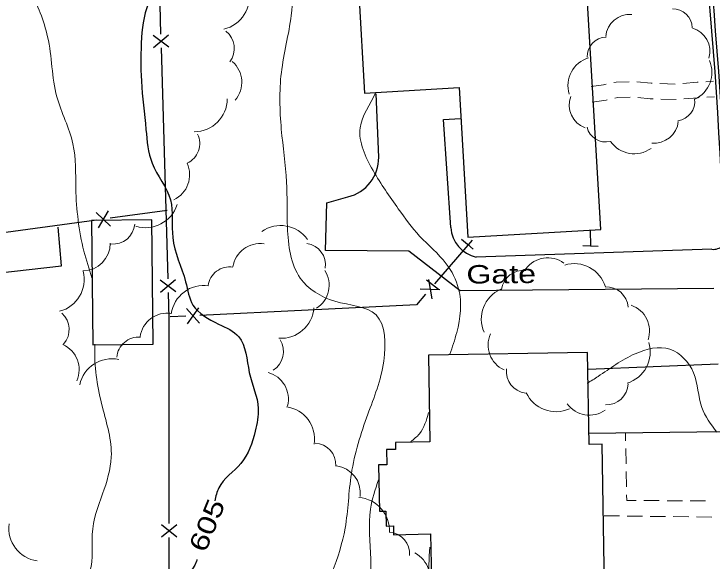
# Model space of a CAD drawing. Extents: x 2361708 to 2370558, y 6977955 to 6991887.
# Drawn here: x 2370196.5 to 2370378, y 6990815 to 6990957.1 of the extents above; entities that cross this region are included whole.
import ezdxf
from ezdxf.enums import TextEntityAlignment as Align

# ---------------------------------------------------------------- set-up
doc = ezdxf.new("R2010")
doc.units = 0
doc.header["$LTSCALE"] = 1.9
for name, color, linetype, lineweight in [('11', 7, 'Continuous', 25), ('13', 7, 'Continuous', 13), ('17', 7, 'Continuous', 25), ('18', 7, 'Continuous', 25), ('2', 7, 'Continuous', 25), ('29', 7, 'Continuous', 13), ('31', 7, 'Continuous', 13), ('35', 7, 'Continuous', 13)]:
    doc.layers.add(name, color=color, linetype=linetype, lineweight=lineweight)

msp = doc.modelspace()

# ---------------------------------------------------------------- linework, layer by layer
at = {"layer": '11'}
for points in [[(2370349.087, 6990901.122), (2370345.238, 6990966.068), (2370320.731, 6990964.615), (2370320.659, 6990965.934), (2370308.225, 6990965.206), (2370308.309, 6990963.716), (2370286.16, 6990962.425), (2370287.667, 6990936.559), (2370312.244, 6990937.983), (2370314.504, 6990899.112)], [(2370232.675, 6990871.312), (2370232.347, 6990903.64), (2370216.668, 6990903.481), (2370216.996, 6990871.153)], [(2370305.237, 6990802.129), (2370350.142, 6990802.887), (2370349.418, 6990845.332), (2370346.018, 6990845.27), (2370345.601, 6990869.157), (2370304.236, 6990868.433), (2370304.62, 6990845.956), (2370295.691, 6990845.8), (2370295.728, 6990843.991), (2370293.359, 6990843.948), (2370293.426, 6990839.979), (2370291.287, 6990839.938), (2370291.511, 6990827.91), (2370293.171, 6990827.946), (2370293.248, 6990824.036), (2370295.148, 6990824.074), (2370295.199, 6990821.785), (2370304.768, 6990822.006)]]:
    msp.add_lwpolyline(points, close=True, dxfattribs=at)
at = {"layer": '13'}
for p, q in [((2370368.429, 6990938.887), (2370364.427, 6990939.039)), ((2370378.402, 6990939.612), (2370376.403, 6990939.503)), ((2370378.63, 6990935.594), (2370376.631, 6990935.485)), ((2370368.657, 6990934.849), (2370364.655, 6990934.991)), ((2370355.511, 6990848.21), (2370355.54, 6990846.21)), ((2370355.579, 6990844.21), (2370355.647, 6990840.211)), ((2370355.676, 6990838.211), (2370355.744, 6990834.212)), ((2370360.288, 6990830.675), (2370364.289, 6990830.663)), ((2370366.288, 6990830.652), (2370370.289, 6990830.64)), ((2370372.289, 6990830.629), (2370376.289, 6990830.617)), ((2370353.926, 6990826.674), (2370349.925, 6990826.716)), ((2370359.927, 6990826.601), (2370355.926, 6990826.653)), ((2370365.928, 6990826.528), (2370361.927, 6990826.58)), ((2370371.929, 6990826.455), (2370367.928, 6990826.507)), ((2370377.93, 6990826.393), (2370373.929, 6990826.435))]:
    msp.add_line(p, q, dxfattribs=at)
for points in [[(2370356.452, 6990939.504), (2370353.033, 6990939.381), (2370352.464, 6990939.265)], [(2370362.426, 6990939.11), (2370362.186, 6990939.118), (2370358.442, 6990939.462)], [(2370374.404, 6990939.384), (2370374.104, 6990939.371), (2370370.417, 6990939.046)], [(2370350.508, 6990938.847), (2370349.759, 6990938.69), (2370346.554, 6990938.229)], [(2370356.68, 6990935.486), (2370353.521, 6990935.375), (2370352.703, 6990935.198)], [(2370362.654, 6990935.073), (2370361.924, 6990935.095), (2370358.671, 6990935.394)], [(2370374.632, 6990935.366), (2370374.392, 6990935.354), (2370370.645, 6990935.029)], [(2370350.747, 6990934.789), (2370350.467, 6990934.726), (2370346.792, 6990934.191)], [(2370355.783, 6990832.211), (2370355.808, 6990830.692), (2370358.288, 6990830.686)]]:
    msp.add_lwpolyline(points, dxfattribs=at)
at = {"layer": '17'}
for p, q in [((2370232.671, 6990951.616), (2370236.76, 6990948.534)), ((2370232.761, 6990948.416), (2370236.67, 6990951.724)), ((2370234.733, 6990948.275), (2370236.493, 6990888.299)), ((2370217.869, 6990905.523), (2370221.573, 6990901.988)), ((2370221.035, 6990905.953), (2370218.407, 6990901.558)), ((2370236.365, 6990906.039), (2370221.503, 6990904.027)), ((2370315.672, 6990898.333), (2370305.859, 6990886.99)), ((2370234.626, 6990884.841), (2370238.525, 6990888.158)), ((2370304.238, 6990888.124), (2370305.167, 6990883.092)), ((2370234.526, 6990888.04), (2370238.625, 6990884.959)), ((2370302.141, 6990885.704), (2370307.264, 6990885.513)), ((2370241.317, 6990880.604), (2370244.714, 6990876.767)), ((2370244.515, 6990880.755), (2370241.515, 6990876.606)), ((2370241.216, 6990878.624), (2370237.097, 6990878.425)), ((2370234.831, 6990824.5), (2370238.831, 6990821.298)), ((2370234.831, 6990821.3), (2370238.831, 6990824.498))]:
    msp.add_line(p, q, dxfattribs=at)
for points in [[(2370286.047, 6990968.025), (2370234.405, 6990959.533), (2370234.628, 6990951.874)], [(2370217.937, 6990903.543), (2370162.376, 6990896.034), (2370162.564, 6990892.106)], [(2370312.879, 6990898.577), (2370314.402, 6990897.281), (2370315.924, 6990895.986)], [(2370306.874, 6990885.479), (2370305.302, 6990886.724), (2370303.73, 6990887.969)], [(2370236.597, 6990884.7), (2370236.79, 6990878.092), (2370236.799, 6990824.699)], [(2370303.505, 6990884.267), (2370301.161, 6990881.555), (2370244.814, 6990878.798)], [(2370236.803, 6990821.099), (2370236.803, 6990807.438), (2370238.374, 6990761.121)]]:
    msp.add_lwpolyline(points, dxfattribs=at)
at = {"layer": '18'}
msp.add_line((2370346.309, 6990900.925), (2370346.388, 6990896.776), dxfattribs=at)
msp.add_lwpolyline([(2370348.389, 6990896.684), (2370346.388, 6990896.776), (2370344.387, 6990896.867)], dxfattribs=at)
at = {"layer": '2'}
for p, q in [((2370291.356, 6990919.883), (2370290.688, 6990936.397)), ((2370377.917, 6990895.975), (2370316.704, 6990893.913)), ((2370379.581, 6990866.13), (2370345.763, 6990864.738)), ((2370381.049, 6990848.533), (2370345.931, 6990848.139))]:
    msp.add_line(p, q, dxfattribs=at)
for points in [[(2370310.05, 6990901.61), (2370308.173, 6990929.694), (2370312.601, 6990929.936)], [(2370378.454, 6990885.761), (2370312.537, 6990885.163), (2370299.208, 6990895.447), (2370277.525, 6990895.67), (2370277.818, 6990908.014), (2370283.343, 6990909.556)], [(2370162.908, 6990886.438), (2370208.9, 6990891.627), (2370207.984, 6990901.758)]]:
    msp.add_lwpolyline(points, dxfattribs=at)
for centre, radius, start, end in [((2369129.002, 6990854.222), 1252.85, 2.32347, 10.08365), ((2369129.002, 6990854.222), 1253.81, 2.32347, 10.08365), ((2370280.754, 6990919.837), 10.602, 284.13856, 0.24886), ((2370318.497, 6990902.187), 8.466, 183.90738, 257.77429), ((2370378.313, 6990899.656), 3.701, 263.86128, 2.00176)]:
    msp.add_arc(centre, radius, start, end, dxfattribs=at)
at = {"layer": '29'}
for centre, radius, start, end in [((2370249.132, 6990961.497), 8.549, 282.84622, 12.84622), ((2370367.823, 6990953.378), 5.042, 1.51209, 91.51209), ((2370356.628, 6990950.725), 6.309, 85.23574, 175.23574), ((2370371.139, 6990947.387), 6.309, 343.97761, 73.97761), ((2370248.093, 6990948.153), 5.696, 322.31786, 52.31786), ((2370350.607, 6990946.074), 5.042, 91.951, 181.951), ((2370248.594, 6990939.372), 7.128, 318.98741, 48.98741), ((2370348.092, 6990938.468), 7.568, 106.82805, 196.82805), ((2370370.407, 6990941.899), 7.568, 294.0519, 24.0519), ((2370347.165, 6990933.467), 6.309, 159.70795, 249.70795), ((2370243.389, 6990935.044), 8.549, 269.96155, 359.96155), ((2370368.459, 6990934.385), 5.042, 277.48768, 7.48768), ((2370362.954, 6990929.849), 6.309, 264.19766, 354.19766), ((2370350.394, 6990928.898), 5.042, 193.3721, 283.3721), ((2370239.097, 6990923.481), 5.696, 295.26838, 25.26838), ((2370357.781, 6990928.354), 7.568, 215.39469, 305.39469), ((2370235.055, 6990915.303), 7.128, 294.91399, 24.91399), ((2370230.729, 6990910.126), 8.549, 252.76101, 342.76101), ((2370222.255, 6990903.01), 5.696, 264.68724, 354.68724), ((2370265.823, 6990893.591), 8.549, 35.03904, 125.03904), ((2370214.39, 6990897.475), 7.128, 270.45772, 0.45772), ((2370260.476, 6990890.326), 7.128, 81.53756, 171.53756), ((2370271.823, 6990891.875), 5.696, 351.44564, 81.44564), ((2370335.291, 6990886.699), 7.064, 53.867, 143.867), ((2370342.156, 6990883.771), 8.472, 16.8681, 106.8681), ((2370206.231, 6990888.147), 8.549, 284.23439, 14.23439), ((2370252.6, 6990885.707), 5.696, 81.76323, 171.76323), ((2370271.312, 6990886.636), 7.128, 302.82576, 32.82576), ((2370328.897, 6990884.842), 5.645, 82.79836, 172.79836), ((2370245.869, 6990878.028), 8.549, 81.87669, 171.87669), ((2370326.474, 6990877.818), 8.472, 113.78306, 203.78306), ((2370350.541, 6990880.541), 5.645, 3.7647, 93.7647), ((2370354.683, 6990874.741), 7.064, 340.89211, 70.89211), ((2370205.165, 6990875.12), 5.696, 318.23674, 48.23674), ((2370236.343, 6990872.253), 7.128, 81.88754, 171.88754), ((2370265.943, 6990881.385), 8.549, 265.99426, 355.99426), ((2370326.845, 6990871.093), 7.064, 155.65023, 245.65023), ((2370228.894, 6990867.443), 5.696, 85.26639, 175.26639), ((2370260.872, 6990869.366), 5.696, 302.24142, 32.24142), ((2370353.459, 6990869.305), 8.472, 286.93233, 16.93233), ((2370206.31, 6990864.72), 7.128, 335.68507, 65.68507), ((2370221.946, 6990858.964), 8.549, 77.88764, 167.88764), ((2370330.147, 6990864.232), 5.645, 173.12725, 263.12725), ((2370260.731, 6990857.058), 7.128, 345.21559, 75.21559), ((2370350.555, 6990861.225), 5.645, 267.57816, 357.57816), ((2370337.394, 6990862.246), 8.472, 204.67876, 294.67876), ((2370346.114, 6990859.93), 7.064, 215.51949, 305.51949), ((2370266.118, 6990846.586), 8.549, 351.78122, 81.78122), ((2370274.505, 6990839.937), 5.696, 357.15051, 87.15051), ((2370279.42, 6990832.647), 7.128, 352.76381, 82.76381), ((2370285.574, 6990822.933), 8.549, 356.17009, 86.17009), ((2370203.719, 6990823.467), 8.549, 172.07629, 262.07629), ((2370293.702, 6990816.81), 5.696, 355.59131, 85.59131), ((2370297.445, 6990810.749), 7.128, 332.29292, 62.29292)]:
    msp.add_arc(centre, radius, start, end, dxfattribs=at)
at = {"layer": '31', "lineweight": 25}
for points in [[(2370171.104, 6991015.093), (2370176.557, 6991014.755), (2370189.569, 6991011.408), (2370198.898, 6991007.367), (2370209.514, 6991004.748), (2370218.7, 6991000.015), (2370223.8, 6990993.724), (2370225.865, 6990985.803), (2370230.908, 6990976.11), (2370235.899, 6990969.607), (2370232.129, 6990961.211), (2370229.677, 6990950.957), (2370229.624, 6990939.686), (2370230.825, 6990927.067), (2370232.417, 6990918.362), (2370237.208, 6990908.797), (2370237.772, 6990899.002), (2370241.141, 6990887.483), (2370243.049, 6990881.471), (2370249.696, 6990876.555), (2370254.948, 6990873.264), (2370257.696, 6990863.98), (2370260.015, 6990854.581), (2370259.241, 6990848.724), (2370255.521, 6990840.338), (2370249.741, 6990833.983), (2370248.694, 6990830.572)], [(2370244.078, 6990815.358), (2370243.952, 6990814.917), (2370237.556, 6990808.175), (2370230.826, 6990800.861), (2370226.412, 6990794.919), (2370223.191, 6990787.608), (2370216.638, 6990780.595), (2370211.555, 6990772.456), (2370207.898, 6990766.831), (2370201.012, 6990762.196), (2370194.039, 6990760.419), (2370189.63, 6990759.197)]]:
    msp.add_spline(points, degree=3, dxfattribs=at)
at = {"layer": '35'}
for points in [[(2370145.358, 6991064.87), (2370141.837, 6991058.666), (2370140.217, 6991048.19), (2370134.967, 6991036.55), (2370136.913, 6991027.558), (2370144.396, 6991017.898), (2370158.274, 6991009.67), (2370167.357, 6991004.157), (2370175.873, 6991000.468), (2370186.721, 6990993.34), (2370193.614, 6990980.425), (2370200.817, 6990963.393), (2370205.264, 6990951.175), (2370207.672, 6990935.567), (2370211.838, 6990923.366), (2370212.589, 6990911.742), (2370214.694, 6990895.492), (2370216.74, 6990888.571)], [(2370233.563, 6991013.317), (2370233.703, 6991013.329), (2370242.779, 6991004.375), (2370247.242, 6990994.667), (2370251.153, 6990987.173), (2370258.271, 6990977.951), (2370265.349, 6990973.968), (2370268.558, 6990966.778), (2370268.604, 6990956.748), (2370266.025, 6990941.873), (2370266.014, 6990927.202), (2370267.365, 6990913.474), (2370267.618, 6990901.656), (2370270.954, 6990888.467), (2370279.941, 6990882.482), (2370290.636, 6990878.904), (2370292.64, 6990866.922), (2370288.501, 6990853.112), (2370284.218, 6990837.621), (2370282.602, 6990823.545), (2370279.211, 6990812.062), (2370273.933, 6990801.371), (2370263.974, 6990789.636), (2370253.121, 6990783.582), (2370244.988, 6990779.645), (2370236.453, 6990771.673), (2370232.012, 6990762.361), (2370227.154, 6990749.483), (2370221.897, 6990740.783), (2370213.653, 6990732.684), (2370205.15, 6990729.823), (2370192.876, 6990727.016), (2370181.795, 6990725.081), (2370169.092, 6990724.169), (2370166.486, 6990723.795)], [(2370290.615, 6990936.777), (2370290.536, 6990936.616), (2370286.512, 6990927.527), (2370289.868, 6990916.439), (2370296.433, 6990906.501), (2370301.981, 6990899.383), (2370308.879, 6990892.219), (2370312.102, 6990885.729), (2370311.62, 6990874.344), (2370309.854, 6990868.706)], [(2370217.555, 6990871.278), (2370217.501, 6990869.528), (2370219.5, 6990854.976), (2370221.803, 6990841.997), (2370219.554, 6990832.435), (2370216.845, 6990821.899), (2370215.595, 6990811.327), (2370208.659, 6990806.691), (2370202.15, 6990799.228), (2370189.516, 6990794.278), (2370177.828, 6990791.936), (2370163.924, 6990788.083)], [(2370379.25, 6990848.426), (2370375.338, 6990854.889), (2370373.183, 6990863.869), (2370367.054, 6990869.991), (2370358.015, 6990868.825), (2370348.36, 6990862.933), (2370345.547, 6990861.165)], [(2370304.297, 6990853.553), (2370301.91, 6990848), (2370299.669, 6990845.988)], [(2370291.254, 6990836.068), (2370289.215, 6990828.488), (2370289.269, 6990815.468), (2370287.838, 6990803.014), (2370280.576, 6990790.534), (2370280.211, 6990789.981)], [(2370304.63, 6990818.605), (2370304.327, 6990809.481), (2370304.16, 6990797.589), (2370301.382, 6990789.972)]]:
    msp.add_spline(points, degree=3, dxfattribs=at)

# ---------------------------------------------------------------- texts
at = {"layer": '17', "width": 1.3}
msp.add_text('Gate', height=4.8, rotation=0.545, dxfattribs=at).set_placement((2370314.159, 6990887.038))
at = {"layer": '31', "width": 1.3}
msp.add_text(' 605 ', height=4.8, rotation=67.712, dxfattribs=at).set_placement((2370248.905, 6990823.359), align=Align.CENTER)

doc.saveas('drawing.dxf')
